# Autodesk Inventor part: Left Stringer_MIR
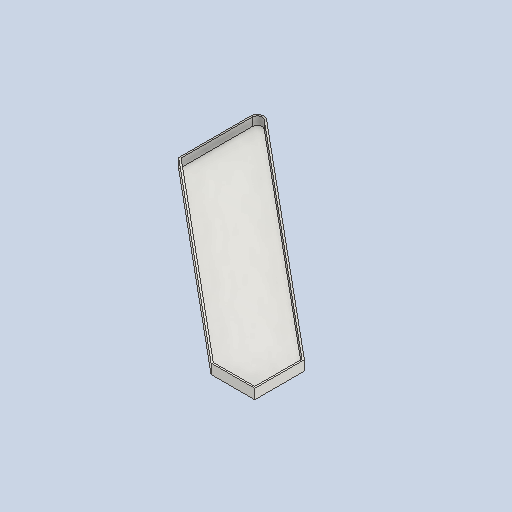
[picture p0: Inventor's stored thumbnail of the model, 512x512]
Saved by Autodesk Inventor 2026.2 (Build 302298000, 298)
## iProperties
Created: 2022-06
Part Number: Left Stringer_MIR
Material: Steel, Galvanized
Document SubType Name: Modeling
Designer: reaumed
Mass: 28099.6 g
Surface Area: 11501.7 cm^2
Volume: 3579.57 cm^3
Density: 7.85 g/cm^3
Appearance: Galvanized
Author: reaumed
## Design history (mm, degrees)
derived "Stringer.ipt"
  sketch "Stringer Profile Sketch"
    geometry: L1 (0, 0)-(914.4, 0) reference; L2 (914.4, 0)-(914.4, -762) reference; L3 (914.4, -762)-(0, -762) reference; L4 (0, -762)-(0, 0) reference; L5 (845.482, -1035.202)-(-68.918, -273.202) reference; L6 (-68.918, -273.202)-(93.689, -78.074) reference; L7 (93.689, -78.074)-(1008.089, -840.074) reference; L8 (1008.089, -840.074)-(845.482, -1035.202) reference; L9 (0, -190.5)-(228.6, -190.5) reference; L10 (0, -190.5)-(0, -330.634) reference; L11 (746.239, -952.5)-(914.4, -952.5) reference; L12 (914.4, -952.5)-(914.4, -762) reference; L13 (0, -1812.658)-(0, 302.11) reference; L14 (2188.973, 0)-(-445.234, 0) reference; L15 (0, -190.5)-(0, -54.23) reference; L16 (93.689, -78.074)-(41.661, -34.717) reference; A1 r 25.4 centre (25.4, -54.23) between (41.661, -34.717) and (0, -54.23) reference; 2 further points
  node "Half the Width Workplane"
feature "Solid2::Stringer.ipt"
tag "TaggingFeature1"
body "Solid2"
